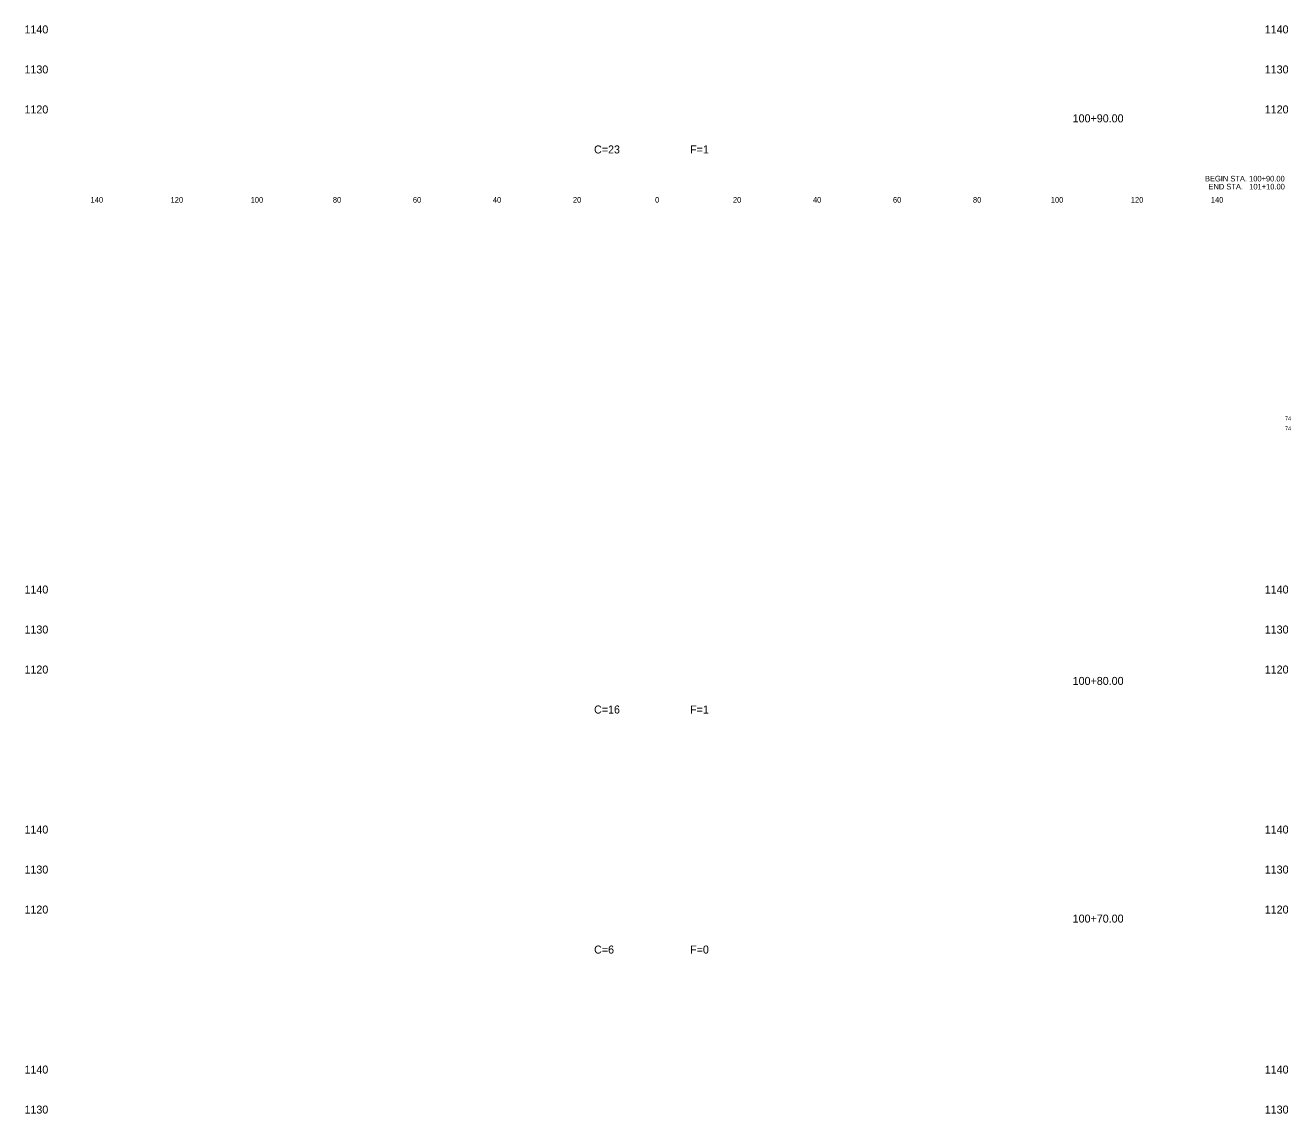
# Model space of a CAD drawing. Extents: x -200 to 1318, y -200 to 2244.
# Drawn here: x 1001.9 to 1318.2, y 1030 to 1302 of the extents above; entities that cross this region are included whole.
import ezdxf

# ---------------------------------------------------------------- set-up
doc = ezdxf.new("R2010")
doc.units = 0
for name, color, linetype in [('Default', 7, 'Continuous'), ('DESIGN - SHEET - Corner Text', 7, 'Continuous'), ('DESIGN - TYPICAL - Text', 7, 'Continuous')]:
    doc.layers.add(name, color=color, linetype=linetype)

msp = doc.modelspace()

# ---------------------------------------------------------------- texts
at = {"layer": 'Default'}
for s, height, p in [('     1140     ', 2, (998.01, 1300)), ('     1140     ', 2, (1308.01, 1300)), ('     1130     ', 2, (998.01, 1290)), ('     1130     ', 2, (1308.01, 1290)), ('     1120     ', 2, (998.01, 1280)), ('     1120     ', 2, (1308.01, 1280)), ('     100+90.00     ', 2, (1260, 1277.77)), ('     140     ', 1.4, (1015.65, 1257.7)), ('     120     ', 1.4, (1035.65, 1257.7)), ('     100     ', 1.4, (1055.65, 1257.7)), ('     80     ', 1.4, (1076.2, 1257.7)), ('     60     ', 1.4, (1096.2, 1257.7)), ('     40     ', 1.4, (1116.2, 1257.7)), ('     20     ', 1.4, (1136.2, 1257.7)), ('     0     ', 1.4, (1156.74, 1257.7)), ('     0     ', 1.4, (1156.74, 1257.7)), ('     20     ', 1.4, (1176.2, 1257.7)), ('     40     ', 1.4, (1196.2, 1257.7)), ('     60     ', 1.4, (1216.2, 1257.7)), ('     80     ', 1.4, (1236.2, 1257.7)), ('     100     ', 1.4, (1255.65, 1257.7)), ('     120     ', 1.4, (1275.65, 1257.7)), ('     140     ', 1.4, (1295.65, 1257.7)), ('     1140     ', 2, (998.01, 1160)), ('     1140     ', 2, (1308.01, 1160)), ('     1130     ', 2, (998.01, 1150)), ('     1130     ', 2, (1308.01, 1150)), ('     1120     ', 2, (998.01, 1140)), ('     1120     ', 2, (1308.01, 1140)), ('     100+80.00     ', 2, (1260, 1137.15)), ('     1140     ', 2, (998.01, 1100)), ('     1140     ', 2, (1308.01, 1100)), ('     1130     ', 2, (998.01, 1090)), ('     1130     ', 2, (1308.01, 1090)), ('     1120     ', 2, (998.01, 1080)), ('     1120     ', 2, (1308.01, 1080)), ('     100+70.00     ', 2, (1260, 1077.74)), ('     1140     ', 2, (998.01, 1040)), ('     1140     ', 2, (1308.01, 1040)), ('     1130     ', 2, (998.01, 1030)), ('     1130     ', 2, (1308.01, 1030))]:
    msp.add_text(s, height=height, dxfattribs=at).set_placement(p)
at = {"layer": 'DESIGN - SHEET - Corner Text'}
for s, height, p in [('BEGIN STA. 100+90.00', 1.4, (1296.78, 1263)), ('END STA.   101+10.00', 1.4, (1297.65, 1261)), ('74', 1, (1316.76, 1203.25)), ('74', 1, (1316.76, 1200.75))]:
    msp.add_text(s, height=height, dxfattribs=at).set_placement(p)
at = {"layer": 'DESIGN - TYPICAL - Text'}
for s, p in [('C=23', (1144.09, 1270)), ('F=1', (1168.09, 1270)), ('C=16', (1144.09, 1130)), ('F=1', (1168.09, 1130)), ('C=6', (1144.1, 1070)), ('F=0', (1168.1, 1070))]:
    msp.add_text(s, height=2, dxfattribs=at).set_placement(p)

doc.saveas('drawing.dxf')
